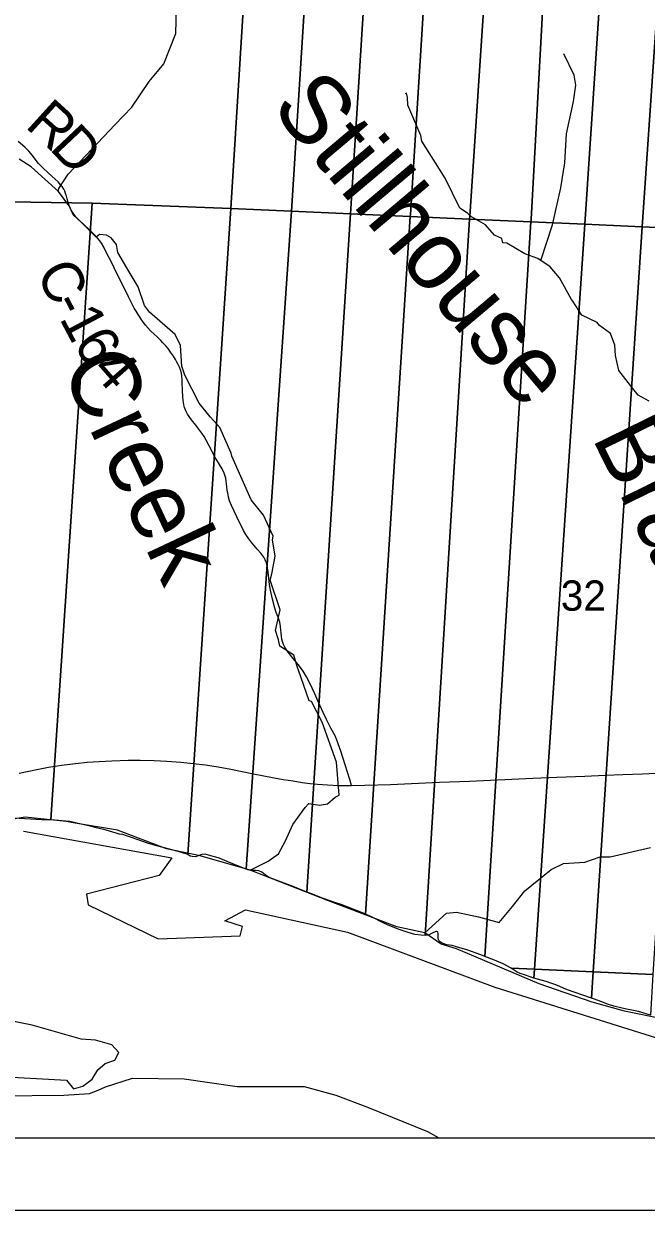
# Model space of a CAD drawing. Extents: x -2.1 to 31.9, y 6.3 to 28.3.
# Drawn here: x 5.147 to 6.006, y 20.344 to 21.982 of the extents above; entities that cross this region are included whole.
import ezdxf

# ---------------------------------------------------------------- set-up
doc = ezdxf.new("R2010")
doc.units = 0
for name, color, linetype in [('Default', 7, 'Continuous'), ('GM_X_County_Road', 7, 'Continuous'), ('GM_X_County_Road_Text', 7, 'Continuous'), ('GM_X_Major_River', 7, 'Continuous'), ('GM_X_Minor_River', 7, 'Continuous'), ('GM_X_Minor_River_Text', 7, 'Continuous'), ('GM_X_Section', 7, 'Continuous'), ('GM_X_Section_Text', 7, 'Continuous'), ('GM_X_State_Route', 7, 'Continuous'), ('SH_Cut_Line', 7, 'Continuous'), ('SH_Data', 7, 'Continuous')]:
    doc.layers.add(name, color=color, linetype=linetype)

msp = doc.modelspace()

# ---------------------------------------------------------------- linework, layer by layer
at = {"layer": 'Default'}
msp.add_lwpolyline([(5.1462, 20.8673), (5.351, 20.8306), (5.3336, 20.8064), (5.2334, 20.7804), (5.2354, 20.7659), (5.3321, 20.7189), (5.4454, 20.7228), (5.4488, 20.7357), (5.4242, 20.7435), (5.4528, 20.7586), (5.5937, 20.7278), (5.7973, 20.6518), (6.0426, 20.5752), (6.4385, 20.4731), (6.4775, 20.444), (6.8344, 20.444), (6.8344, 25.7721)], dxfattribs=at)
at = {"layer": 'GM_X_County_Road'}
msp.add_lwpolyline([(5.5994, 20.9305), (5.5969, 20.9387), (5.5906, 20.9591), (5.5846, 20.9781), (5.581, 20.9882), (5.5784, 20.9945), (5.5765, 20.9991), (5.5709, 21.0097), (5.5648, 21.0215), (5.5602, 21.0313), (5.553, 21.0466), (5.548, 21.0581), (5.5425, 21.0698), (5.5372, 21.0805), (5.5323, 21.0884), (5.5274, 21.0951), (5.5169, 21.108), (5.5103, 21.1165), (5.5072, 21.1213), (5.5053, 21.1252), (5.504, 21.1291), (5.5032, 21.1324), (5.5027, 21.1365), (5.5023, 21.1408), (5.5012, 21.15), (5.5002, 21.1562), (5.4979, 21.1631), (5.4954, 21.1693), (5.4935, 21.1752), (5.4902, 21.1878), (5.4874, 21.2003), (5.4861, 21.208), (5.4849, 21.2169), (5.484, 21.2251), (5.4829, 21.2337), (5.482, 21.2378), (5.4801, 21.242), (5.478, 21.2456), (5.474, 21.2511), (5.4692, 21.2567), (5.4648, 21.2618), (5.4617, 21.2654), (5.4573, 21.271), (5.4534, 21.277), (5.4501, 21.2828), (5.4407, 21.3014), (5.4334, 21.3171), (5.4309, 21.3237), (5.4293, 21.3285), (5.4288, 21.3321), (5.4276, 21.3385), (5.4266, 21.347), (5.4262, 21.3509), (5.4256, 21.3547), (5.4249, 21.3576), (5.4235, 21.3617), (5.4208, 21.3678), (5.4135, 21.3796), (5.4102, 21.3849), (5.4068, 21.3915), (5.4027, 21.3994), (5.3987, 21.4071), (5.3956, 21.4125), (5.3927, 21.4168), (5.3899, 21.4209), (5.3842, 21.4282), (5.3783, 21.4353), (5.3726, 21.4434), (5.3705, 21.4478), (5.3687, 21.4523), (5.3679, 21.4562), (5.3673, 21.4594), (5.3664, 21.4666), (5.366, 21.4763), (5.3656, 21.4867), (5.3654, 21.4906), (5.3649, 21.4958), (5.3643, 21.4997), (5.3631, 21.5044), (5.3616, 21.5081), (5.3598, 21.5117), (5.3582, 21.5151), (5.3561, 21.5189), (5.3535, 21.5231), (5.3495, 21.5289), (5.3459, 21.5337), (5.3428, 21.5375), (5.3388, 21.5418), (5.3359, 21.545), (5.3307, 21.5498), (5.3269, 21.5535), (5.3219, 21.5584), (5.3148, 21.5663), (5.3097, 21.5729), (5.3047, 21.5808), (5.3018, 21.5855), (5.2993, 21.5898), (5.2947, 21.5986), (5.2911, 21.6054), (5.2872, 21.6139), (5.2762, 21.6358), (5.2669, 21.6551), (5.2625, 21.6633), (5.257, 21.6736), (5.2539, 21.6792), (5.2517, 21.6825), (5.2473, 21.688), (5.2374, 21.6979), (5.2233, 21.7112), (5.2185, 21.7159), (5.2147, 21.7207), (5.2122, 21.7247), (5.2107, 21.7278), (5.2093, 21.7313), (5.208, 21.7353), (5.2068, 21.7406), (5.2059, 21.7442), (5.2045, 21.7481), (5.2035, 21.7512), (5.2021, 21.7538), (5.1997, 21.7575), (5.1976, 21.76), (5.1941, 21.764), (5.186, 21.7714), (5.1794, 21.7773), (5.1745, 21.782), (5.1705, 21.7856), (5.1669, 21.7895), (5.1638, 21.7934), (5.1586, 21.8005), (5.1536, 21.8064), (5.1479, 21.8119), (5.1389, 21.8196)], dxfattribs=at)
at = {"layer": 'GM_X_Major_River'}
for points in [[(6.1198, 20.5893), (5.9765, 20.6191), (5.9318, 20.6312), (5.8582, 20.6565), (5.7444, 20.7049), (5.7232, 20.7113), (5.7005, 20.7269), (5.6618, 20.7352), (5.5677, 20.7714), (5.4593, 20.8134), (5.3903, 20.8334), (5.344, 20.8432), (5.2762, 20.8686), (5.2147, 20.8791), (5.2053, 20.8806), (5.1488, 20.8866), (5.1242, 20.8828)], [(5.1052, 20.529), (5.2057, 20.5236), (5.2152, 20.5115), (5.228, 20.5153), (5.2409, 20.5252), (5.2489, 20.5377), (5.2591, 20.5468), (5.2724, 20.551), (5.278, 20.5616), (5.2685, 20.5722), (5.2458, 20.5787), (5.2257, 20.5802), (5.1582, 20.5994), (5.1147, 20.6081)], [(5.1135, 20.5021), (5.2019, 20.5027), (5.2375, 20.5054), (5.2493, 20.5096), (5.2595, 20.5146), (5.297, 20.5264), (5.3683, 20.5253), (5.4414, 20.5148), (5.5339, 20.5149), (5.5775, 20.5029), (5.6215, 20.4862), (5.7042, 20.4529), (5.7198, 20.444)]]:
    msp.add_lwpolyline(points, dxfattribs=at)
at = {"layer": 'GM_X_Minor_River'}
for points in [[(5.194, 21.7506), (5.1952, 21.7546), (5.208, 21.7747), (5.2728, 21.8432), (5.2958, 21.8672), (5.32, 21.9028), (5.3403, 21.9269), (5.3567, 21.9689), (5.3578, 22.0049)], [(5.8609, 21.6554), (5.8768, 21.7047), (5.8885, 21.7559), (5.8941, 21.7903), (5.8961, 21.8301), (5.9057, 21.875), (5.9091, 21.8977), (5.9069, 21.9114), (5.8926, 21.9407)], [(5.9383, 21.57), (5.9173, 21.5797), (5.9048, 21.5994), (5.9029, 21.6017), (5.8866, 21.6313), (5.8737, 21.6465), (5.8567, 21.6582), (5.8386, 21.6647), (5.814, 21.6794), (5.8083, 21.6798), (5.8068, 21.6859), (5.7966, 21.6904), (5.7845, 21.7048), (5.7648, 21.7158), (5.7595, 21.7207), (5.7489, 21.7279), (5.7285, 21.7689), (5.6963, 21.8201), (5.6951, 21.8281), (5.677, 21.8699), (5.6766, 21.8805), (5.6751, 21.8866), (5.6732, 21.8855)], [(5.4593, 20.8134), (5.484, 20.8262), (5.4983, 20.8361), (5.5081, 20.854), (5.5183, 20.8765), (5.5353, 20.9001), (5.5402, 20.9058), (5.555, 20.9032), (5.5663, 20.9051), (5.5769, 20.9142), (5.5822, 20.9173), (5.5784, 20.9625), (5.5586, 21.0179), (5.5439, 21.0464), (5.5409, 21.0475), (5.5261, 21.0897), (5.5249, 21.0935), (5.5196, 21.1106), (5.5003, 21.1231), (5.4984, 21.1314), (5.4943, 21.1444), (5.5007, 21.1729), (5.487, 21.2139), (5.4893, 21.2226), (5.4938, 21.2473), (5.49, 21.2698), (5.4911, 21.2747), (5.4779, 21.3039), (5.4605, 21.3248), (5.4339, 21.3852), (5.4332, 21.3893), (5.4173, 21.4246), (5.404, 21.4394), (5.3889, 21.4584), (5.3692, 21.4971), (5.365, 21.5097), (5.3631, 21.5382), (5.3559, 21.5533), (5.3204, 21.584), (5.3135, 21.5935), (5.3048, 21.619), (5.292, 21.6398), (5.2764, 21.6664), (5.2745, 21.6774), (5.2673, 21.6869), (5.2609, 21.6903), (5.2511, 21.6914), (5.2465, 21.6876), (5.2257, 21.7085), (5.2148, 21.7183), (5.2102, 21.7293), (5.1947, 21.7506), (5.1569, 21.7847), (5.1402, 21.7953)], [(6.0104, 21.461), (5.9952, 21.4693), (5.9877, 21.4788), (5.9684, 21.5034), (5.9638, 21.5243), (5.963, 21.5384), (5.957, 21.5547), (5.9418, 21.5657), (5.9382, 21.5701)], [(5.7005, 20.7269), (5.7305, 20.7542), (5.7441, 20.7558), (5.7747, 20.749), (5.8031, 20.7415), (5.8216, 20.7632), (5.8386, 20.7849), (5.8752, 20.8146), (5.8922, 20.823), (5.9217, 20.8246), (5.9429, 20.8322), (5.9565, 20.8322), (6.0124, 20.8449)]]:
    msp.add_lwpolyline(points, dxfattribs=at)
at = {"layer": 'GM_X_Section'}
for points in [[(4.4397, 22.818), (5.498, 22.7781), (5.4326, 21.7271), (5.2409, 21.7347), (5.043, 21.7379), (4.8395, 21.7479), (4.6504, 21.7575), (4.4881, 21.7655), (4.3744, 21.7716), (4.4255, 22.5906)], [(5.5827, 22.774), (5.5162, 21.7235), (5.4326, 21.7271), (5.498, 22.7781)], [(5.664, 22.7698), (5.5978, 21.7199), (5.5162, 21.7235), (5.5827, 22.774)], [(5.7467, 22.7656), (5.6807, 21.7191), (5.6805, 21.7162), (5.5978, 21.7199), (5.664, 22.7698)], [(5.8324, 22.7612), (5.7625, 21.7168), (5.7622, 21.7126), (5.6805, 21.7162), (5.6807, 21.7191), (5.7467, 22.7656)], [(5.9044, 22.7576), (5.8472, 21.7121), (5.847, 21.7088), (5.7622, 21.7126), (5.7625, 21.7168), (5.8324, 22.7612)], [(5.9912, 22.7527), (5.9213, 21.7055), (5.847, 21.7088), (5.8472, 21.7121), (5.9044, 22.7576)], [(6.0723, 22.7483), (6.0006, 21.7019), (5.9213, 21.7055), (5.9912, 22.7527)], [(6.1513, 22.7445), (6.0839, 21.6982), (6.0813, 21.6984), (6.0006, 21.7019), (6.0723, 22.7483)], [(5.043, 21.7379), (5.2409, 21.7347), (5.1841, 20.8829), (5.1718, 20.8832), (5.1324, 20.8853), (5.1275, 20.8861), (5.1249, 20.8854), (5.117, 20.8862), (5.0992, 20.8854), (5.0844, 20.8853), (5.0764, 20.8857), (5.0598, 20.8849), (5.0499, 20.8841), (5.031, 20.8833), (5.0143, 20.8829), (4.9961, 20.8848), (4.9832, 20.8861)], [(5.2409, 21.7347), (5.4326, 21.7271), (5.3732, 20.8354), (5.3633, 20.8384), (5.3462, 20.8429), (5.3288, 20.8477), (5.3174, 20.8507), (5.2969, 20.8582), (5.2886, 20.8612), (5.2833, 20.8627), (5.2784, 20.8631), (5.2742, 20.8646), (5.2605, 20.8687), (5.2473, 20.8721), (5.2385, 20.8743), (5.226, 20.8769), (5.2101, 20.8807), (5.1999, 20.8818), (5.1841, 20.8829)], [(5.5162, 21.7235), (5.4539, 20.815), (5.4433, 20.8193), (5.4274, 20.8257), (5.4209, 20.8284), (5.4149, 20.8306), (5.405, 20.8332), (5.397, 20.8355), (5.3925, 20.8351), (5.3876, 20.8332), (5.3838, 20.832), (5.3792, 20.8324), (5.3766, 20.8331), (5.3732, 20.8354), (5.4326, 21.7271)], [(5.5978, 21.7199), (5.5378, 20.7834), (5.5188, 20.7912), (5.5025, 20.7972), (5.4854, 20.8036), (5.4801, 20.807), (5.4756, 20.8107), (5.4714, 20.8126), (5.4668, 20.813), (5.4604, 20.8133), (5.4562, 20.8141), (5.4539, 20.815), (5.5162, 21.7235)], [(5.6805, 21.7162), (5.6188, 20.7528), (5.6144, 20.7548), (5.6038, 20.7589), (5.5852, 20.766), (5.5761, 20.769), (5.5591, 20.7747), (5.5416, 20.7818), (5.5378, 20.7834), (5.5978, 21.7199)], [(5.7622, 21.7126), (5.7009, 20.7233), (5.6953, 20.7236), (5.6869, 20.7247), (5.6774, 20.7273), (5.6653, 20.7315), (5.6501, 20.7375), (5.6429, 20.7408), (5.627, 20.7491), (5.6188, 20.7528), (5.6805, 21.7162)], [(5.847, 21.7088), (5.7833, 20.6945), (5.7779, 20.6966), (5.7601, 20.703), (5.7521, 20.7056), (5.7442, 20.7075), (5.7385, 20.7094), (5.7309, 20.7105), (5.726, 20.7123), (5.7218, 20.7146), (5.7199, 20.7165), (5.7191, 20.7191), (5.7191, 20.726), (5.7187, 20.7279), (5.718, 20.7286), (5.7168, 20.729), (5.7157, 20.729), (5.7108, 20.7267), (5.7055, 20.724), (5.7009, 20.7233), (5.7622, 21.7126)], [(5.9213, 21.7055), (5.852, 20.6768), (5.8198, 20.6782), (5.8087, 20.6842), (5.7969, 20.6891), (5.7833, 20.6945), (5.847, 21.7088)], [(6.0006, 21.7019), (5.933, 20.6732), (5.852, 20.6768), (5.9213, 21.7055)], [(6.0813, 21.6984), (6.0156, 20.6695), (5.933, 20.6732), (6.0006, 21.7019)], [(5.852, 20.6768), (5.8511, 20.6646), (5.8459, 20.6662), (5.8383, 20.6692), (5.8322, 20.6707), (5.828, 20.6729), (5.8198, 20.6782)], [(5.933, 20.6732), (5.9306, 20.6368), (5.9187, 20.641), (5.9081, 20.6448), (5.8963, 20.6489), (5.8872, 20.653), (5.8815, 20.6553), (5.8747, 20.6575), (5.8679, 20.6598), (5.8561, 20.6632), (5.8511, 20.6646), (5.852, 20.6768)], [(6.0156, 20.6695), (6.012, 20.6134), (5.9957, 20.6186), (5.9862, 20.6204), (5.979, 20.6215), (5.973, 20.623), (5.9616, 20.626), (5.954, 20.6283), (5.9438, 20.6324), (5.9347, 20.6354), (5.9306, 20.6368), (5.933, 20.6732)]]:
    msp.add_lwpolyline(points, close=True, dxfattribs=at)
at = {"layer": 'GM_X_State_Route'}
msp.add_lwpolyline([(5.1402, 20.9475), (5.1646, 20.9526), (5.181, 20.9556), (5.1989, 20.9584), (5.218, 20.9608), (5.2344, 20.9625), (5.2509, 20.9638), (5.2683, 20.9647), (5.2907, 20.9653), (5.3075, 20.9653), (5.3267, 20.9649), (5.3441, 20.964), (5.3636, 20.9626), (5.3808, 20.9609), (5.3977, 20.9589), (5.4151, 20.9561), (5.4324, 20.953), (5.4639, 20.9468), (5.49, 20.9417), (5.5049, 20.939), (5.5187, 20.9367), (5.5309, 20.9348), (5.542, 20.9334), (5.5525, 20.9322), (5.5661, 20.9313), (5.5815, 20.9307), (5.5994, 20.9305), (5.6175, 20.9308), (5.6529, 20.932), (5.7206, 20.9349), (5.7622, 20.9366), (5.8497, 20.9404), (5.8826, 20.9419), (5.9217, 20.9436), (5.9496, 20.9447), (5.9738, 20.9456), (6.0012, 20.9468), (6.0385, 20.9484)], dxfattribs=at)
at = {"layer": 'SH_Cut_Line'}
msp.add_lwpolyline([(5.1462, 20.8673), (5.351, 20.8306), (5.3336, 20.8064), (5.2334, 20.7804), (5.2354, 20.7659), (5.3321, 20.7189), (5.4454, 20.7228), (5.4488, 20.7357), (5.4242, 20.7435), (5.4528, 20.7586), (5.5937, 20.7278), (5.7973, 20.6518), (6.0426, 20.5752), (6.4385, 20.4731), (6.4775, 20.444), (6.8344, 20.444), (6.8344, 27.244)], dxfattribs=at)
at = {"layer": 'SH_Data'}
for p, q in [((0.0344, 20.444), (6.8344, 20.444)), ((-0.0656, 20.344), (6.9344, 20.344))]:
    msp.add_line(p, q, dxfattribs=at)

# ---------------------------------------------------------------- texts
at = {"layer": 'GM_X_County_Road_Text'}
for s, rotation, p in [('R', 317.7996, (5.1471, 21.8403)), ('D', 313.3796, (5.1809, 21.8098)), ('C', 297.5557, (5.1626, 21.6381)), ('-', 297.6185, (5.1843, 21.5966)), ('1', 297.852, (5.1952, 21.5757)), ('6', 302.5796, (5.2141, 21.5404)), ('4', 311.2111, (5.2386, 21.5034))]:
    msp.add_text(s, height=0.0568, rotation=rotation, dxfattribs=at).set_placement(p)
at = {"layer": 'GM_X_Minor_River_Text'}
for s, rotation, p in [('Stillhouse', 310.1347, (5.4863, 21.8661)), ('Creek', 295.1343, (5.1971, 21.5082)), ('Branch', 296.1346, (5.9307, 21.4114))]:
    msp.add_text(s, height=0.09469, rotation=rotation, dxfattribs=at).set_placement(p)
at = {"layer": 'GM_X_Section_Text'}
msp.add_text('32', height=0.04186, rotation=0, dxfattribs=at).set_placement((5.8883, 21.1718))

doc.saveas('drawing.dxf')
